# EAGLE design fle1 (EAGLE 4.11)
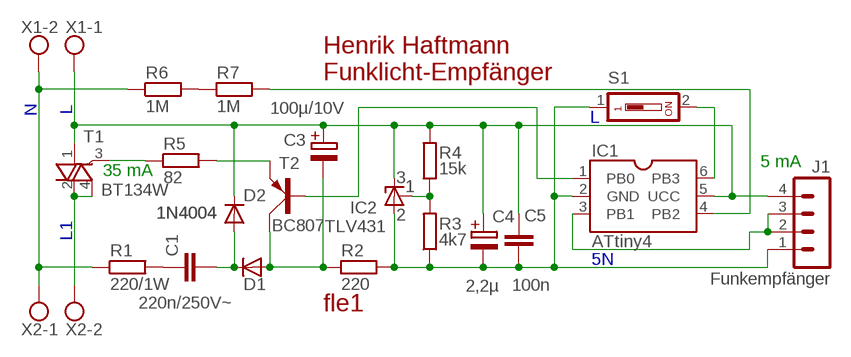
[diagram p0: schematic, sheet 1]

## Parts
C1  220n/250V~  C15  [C150-084X183]
C3  100µ/10V  E01-5  [E01-5]
C4  2,2µ  E01-5  [E01-5]
C5  100n  C0805  [0805]
D1  1N4004  D  [MINIMELF]
D2  1N4004  D  [MINIMELF]
IC1  ATtiny4  ATTINY4  [SOT23-6]
IC2  TLV431  TL431DBZ  [SOT23@1]
J1  Funkempfänger  MA04-1  [MA04-1]
R1  220/1W  R05  [R05]
R2  220  R1206  [1206]
R3  4k7  R0805  [0805]
R4  15k  R0805  [0805]
R5  82  R1206  [1206]
R6  1M  R04  [R04]
R7  1M  R04  [R04]
S1  DS01  [DS-01]
T1  BT134W  TRIAC4  [SOT223]
T2  BC807  PNPS  [SOT23]
X1  W237-02P  [W237-132]
X2  W237-02P  [W237-132]

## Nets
5N: C4.- C5.2 IC1.2(GND) IC2.3(A) J1.1 R2.2 R3.1 S1.1
L: C3.+ C4.+ C5.1 D2.K IC1.5(UCC) IC2.1(K) J1.4 R4.1 T1.1(K) X1.1
L1: T1.2(A) T1.4(A) X2.2
N: R1.1 R6.1 X1.2 X2.1
N$1: C1.1 R1.2
N$2: IC1.4(PB2) R7.2
N$3: IC2.2(R) R3.2 R4.2
N$4: C3.- D1.A R2.1 T2.3(C)
N$5: R6.2 R7.1
N$6: IC1.1(PB0) T2.1(B)
N$7: C1.2 D1.K D2.A
N$8: R5.2 T2.2(E)
N$9: R5.1 T1.3(G)
N$10: IC1.6(PB3) S1.2
N$12: IC1.3(PB1) J1.2 J1.3

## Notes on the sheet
- Henrik Haftmann
- Funklicht-Empfänger
- 5 mA
- 35 mA
- 3
- 1
- 2

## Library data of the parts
C1 C5 = fu:C: Kondensator
C3 C4 = fu:E: Elektrolytkondensator, gepolt
D1 D2 = fu:D: Diode
IC1 = fu:ATTINY4: AVR-Mikrocontroller TypFlashRAMADCSignatur ATtiny451232nein0x1E 0x8F 0x0A ATtiny551232ja0x1E 0x8F 0x09 ATtiny9102432nein0x1E 0x90 0x08 ATtiny10102432ja0x1E 0x90 0x03
IC2 = fu:TL431: Querregler
J1 = con-lstb:MA04-1: PIN HEADER
R1-R7 = fu:R: Widerstand
S1 = switch-dil:DS01: DIL/CODE SWITCH
T1 = fu:TRIAC4: Triac 4 Pins
T2 = fu:PNP: pnp-Transistor
X1 X2 = con-wago-508:W237-02P: WAGO SREW CLAMP

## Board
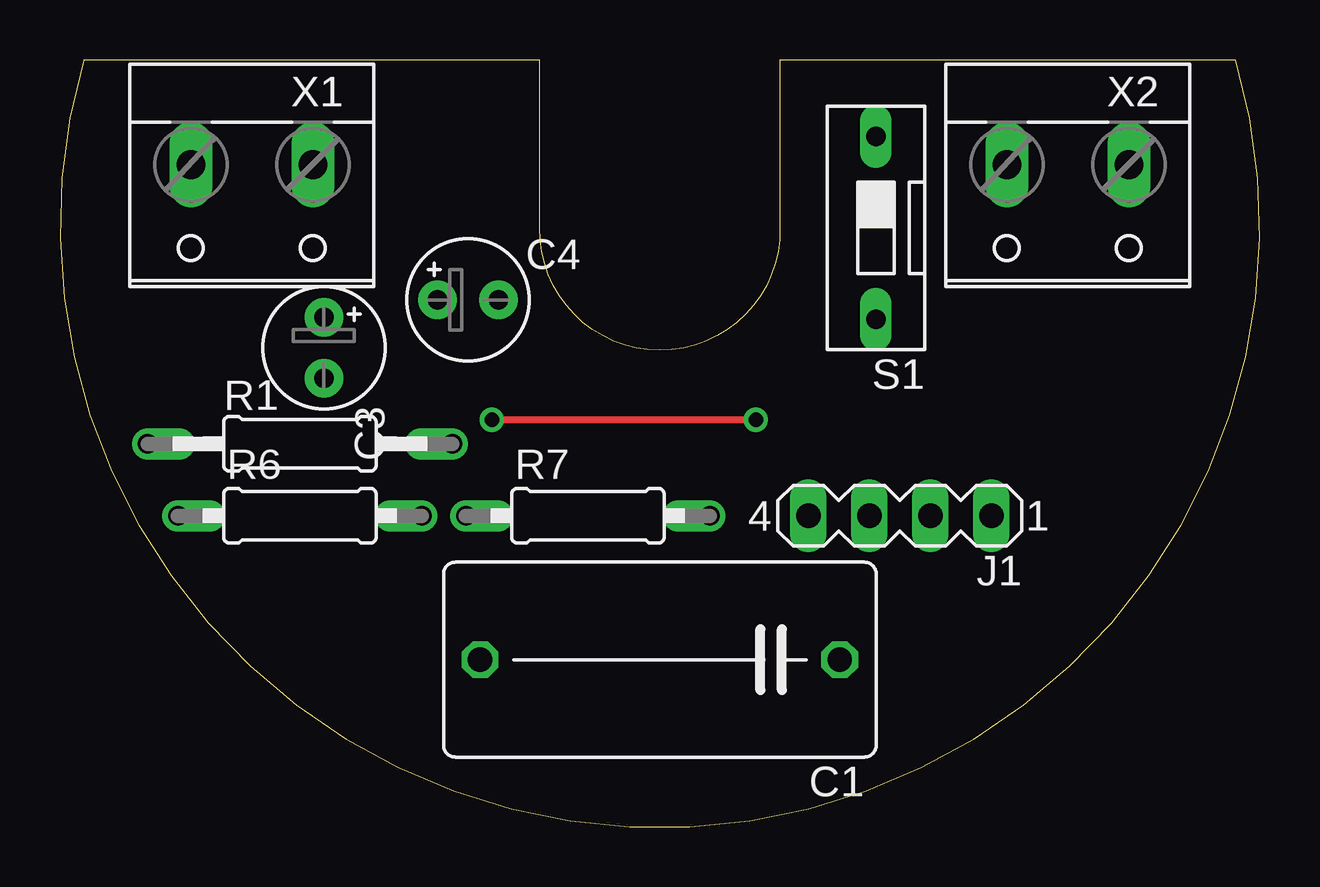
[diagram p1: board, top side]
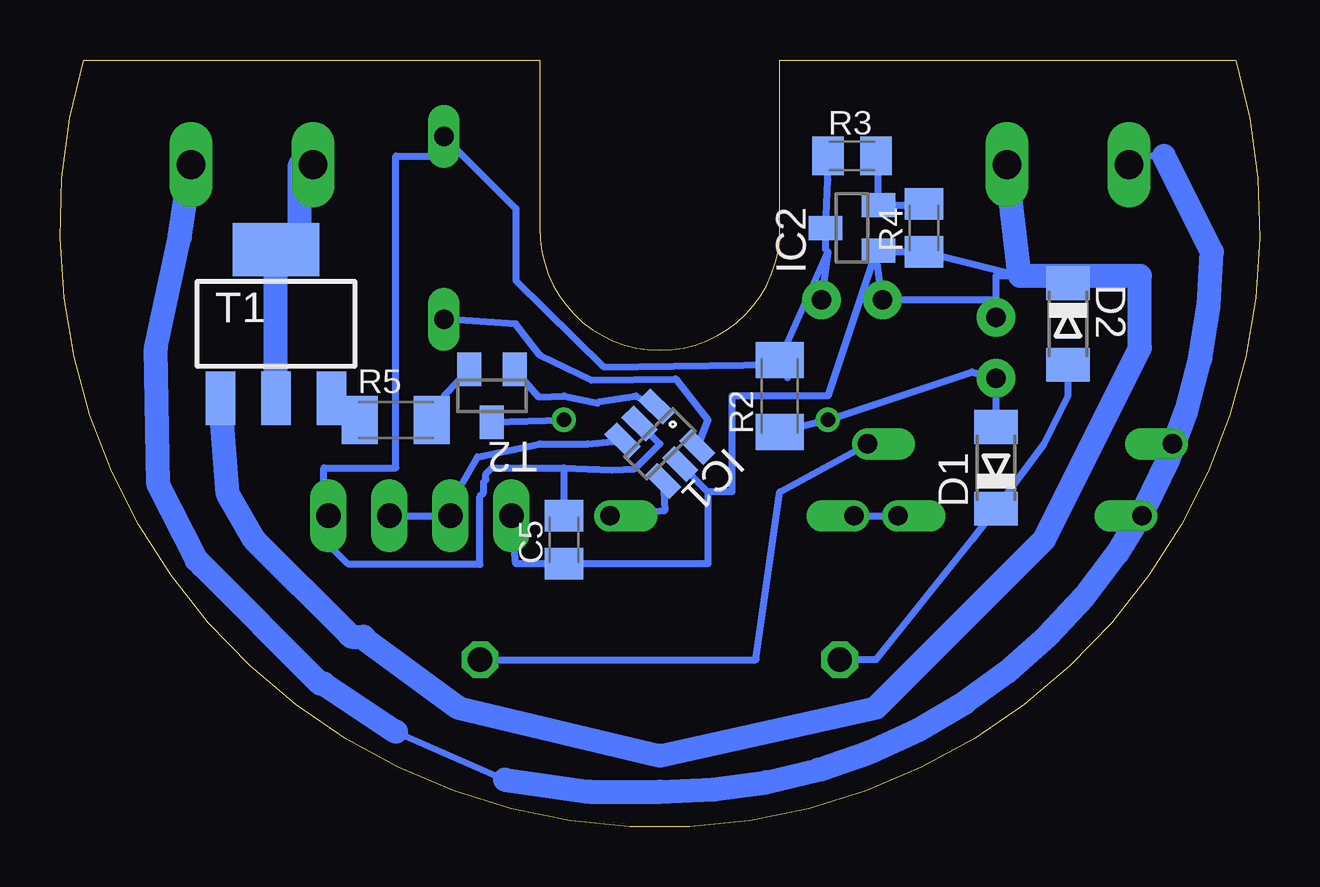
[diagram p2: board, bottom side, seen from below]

Size 49.99 x 31.97 mm. Coordinates in mm from the lower left corner, seen from the top.
Outline: 1,31.97 arc213 49,31.97 30,31.97 30,24.97 arc-182 20,24.97 20,31.97 1,31.97
Copper layers (1*16): Top 0.035mm / dielectric 1.5mm / Bottom 0.035mm
Design rules "default": minimum track width 10mil, minimum drill 0.6mm, track to track 8mil, track to pad 8mil, pad to pad 8mil, via to via 8mil, smd to smd 0mil, copper to edge 0.5mm, drill to drill 8mil, minimum pad ring 10mil, minimum via ring 8mil, stop-mask expansion 4mil, vias tented up to drill 0mil, thermal gap 10mil

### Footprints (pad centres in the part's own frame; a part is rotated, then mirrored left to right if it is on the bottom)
C150-084X183 = drill 1.016 octagon: 1 -7.493,0; 2 7.493,0
E01-5 = drill 0.813 pad 1.6 round: + -1.27,0; - 1.27,0
0805 = smd 1.3 x 1.6: 1 -1,0; 2 1,0
MINIMELF = smd 1.4 x 1.8: A 1.7,0; K -1.7,0
SOT23-6 = smd 0.711 x 1.422: 1 -1,-1.2; 2 0,-1.2; 3 1,-1.2; 4 1,1.2; 5 0,1.2; 6 -1,1.2
SOT23@1 = smd 1 x 1.4: 1 -0.95,-1.1; 2 0.95,-1.1; 3 0,1.1
MA04-1 = drill 1.016 long: 1 -3.81,0; 2 -1.27,0; 3 1.27,0; 4 3.81,0
R05 = drill 0.813 offset: 1 -6.35,0; 2 6.35,0
1206 = smd 1.5 x 2: 1 -1.5,0; 2 1.5,0
R04 = drill 0.813 offset: 1 -5.08,0; 2 5.08,0
DS-01 = drill 0.813 long: 1 0,-3.81; 2 0,3.81
SOT223 = smd 1.219 x 2.235: 1 -2.311,-3.099; 2 0,-3.099; 3 2.311,-3.099 | smd 3.6 x 2.2: 4 0,3.099
SOT23 = smd 1 x 1.4: 1 -0.95,-1.1; 2 0.95,-1.1; 3 0,1.1
W237-132 = drill 1.194 long: 1 -2.54,-0.635; 2 2.54,-0.635

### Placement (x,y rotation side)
C1  25,6.97 180 top
C3  11,19.97 270 top
C4  17,21.97 0 top
C5  29,11.97 90 bottom
D1  11,14.97 90 bottom
D2  8,20.97 270 bottom
IC1  25,15.97 225 bottom
IC2  17,24.97 90 bottom
J1  35,12.97 180 top
R1  10,15.97 0 top
R2  20,17.97 90 bottom
R3  17,27.97 0 bottom
R4  14,24.97 90 bottom
R5  36,16.97 0 bottom
R6  10,12.97 0 top
R7  22,12.97 0 top
S1  34,24.97 180 top
T1  41,20.97 0 bottom
T2  32,17.97 180 bottom
X1  8,26.97 180 top
X2  42,26.97 180 top

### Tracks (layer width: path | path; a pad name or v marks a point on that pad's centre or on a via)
5N
  Bottom 0.3: R3.1 18,26.97 IC2.3 18.1,24.07 18,23.97 | 18,23.97 R2.2 19.68,18.73 19.92,18.97 20,19.97 20.05,19.27 27.35,19.17 31,22.77 31,25.78 S1.1 | 18,23.97 C4.- | IC1.2 25,15.97 26.05,14.92 27,14.87 29,14.97 | 29,14.97 C5.2 | 39,13.16 J1.1 | 39,13.16 39,14.97 36,14.97 36,27.97 34,27.97 S1.1 | S1.1 34,28.97 | 29,14.97 32,14.97 32.25,14.72 32.25,14.47 32.35,14.37 32.35,13.92 32.5,13.77 32.5,10.92 32.55,10.97 38,10.97 39,11.97 39,13.16
L
  Bottom 0.3: 10,22.97 R4.1 16,23.97 | 43,17.97 43.1,17.87 T1.1 | 23,13.97 23,10.97 C5.1 31,10.97 J1.4 | 23,13.97 IC1.5 | 38,7.97 37.95,8.02 | D2.K 8,22.97 10,22.97 | 10,22.97 11,22.97 11,21.97 | 11,20.97 C3.+ 11,21.97 | 16,23.97 C4.+ 11,21.97 | 16,23.97 IC2.1 | 23,13.97 22,13.97 22,17.97 18,17.97 16,23.97
  Bottom 1: T1.1 43,13.87 41.9,11.97 37.95,8.02 37.85,7.92 37.35,7.92 37.23,7.78 33.4,4.97 25,2.97 16,4.97 9,11.97 5,19.97 5,22.97 10,22.97 10.54,27.51 X1.1
L1
  Bottom 1: X2.2 40,27.6 40,23.97 41,23.97 | 41,23.97 T1.4 | T1.2 41,23.97
N
  Bottom 0.3: 39,5.97 44.07,10.89 | 36,3.97 31.45,1.97 | 2,23.97 2,21.97 3,16.97 R6.1 5,12.97 R1.1 | 4,27.97 5,27.97 X1.2
  Bottom 1: X2.1 45,24.6 46,19.97 45.9,14.27 44.3,11.12 44.07,10.89 39.15,5.97 39,5.97 36,3.97 | 31.45,1.97 27.95,1.47 25,1.47 arc-90 2,23.97 4,27.97
N$1
  Bottom 0.3: R1.2 20,13.97 21,6.97 C1.1
N$2
  Bottom 0.3: IC1.4 24.8,13.17 R7.2
N$3
  Bottom 0.3: R3.2 15.95,27.92 IC2.2 14.05,25.92 R4.2
N$4  (via drill 0.6 pad 0.6)
  Top 0.3: v29,16.97 v18,16.97
  Bottom 0.3: T2.3 v29,16.97 | C3.- 11,18.97 | C3.- D1.A | C3.- 12,18.97 v18,16.97 R2.1
N$5
  Bottom 0.3: R7.1 R6.2
N$6
  Bottom 0.3: T2.1 30.05,17.92 29,17.97 27.59,17.66 27.52,17.73 26,17.97 IC1.1
N$7
  Bottom 0.3: D2.A 8,17.97 9,15.97 D1.K 12,11.97 16,6.97 C1.2
N$8
  Bottom 0.3: T2.2 33.95,18.02 R5.2
N$9
  Bottom 0.3: T1.3 38.69,17.28 R5.1
N$10
  Bottom 0.3: IC1.6 23,16.97 24.35,18.67 27.85,18.62 30,19.67 31,20.97 S1.2
N$12
  Bottom 0.3: 34,12.97 J1.3 | 34,12.97 32.6,15.42 30,15.97 28,15.97 IC1.3 | J1.2 34,12.97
